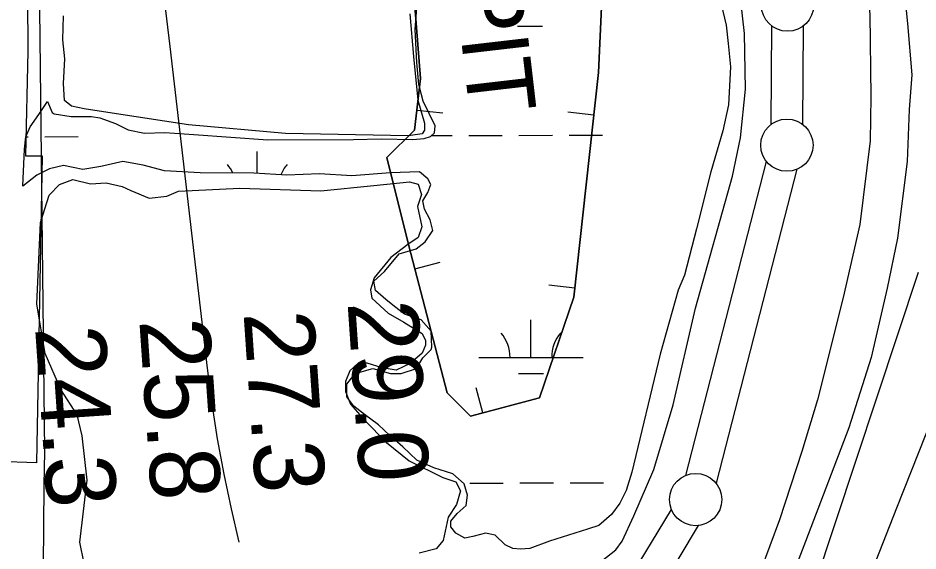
# Model space of a CAD drawing. Extents: x 3355724 to 3393621, y 594744 to 620174.
# Drawn here: x 3387561 to 3388422, y 601973 to 602483 of the extents above; entities that cross this region are included whole.
import ezdxf

# ---------------------------------------------------------------- set-up
doc = ezdxf.new("R2010")
doc.units = 0
for name, color, linetype in [('V-BORW-IDEN', 7, 'Continuous'), ('V-BORW-LINE', 7, 'Continuous'), ('V-LEVE-TOET', 7, 'Continuous'), ('V-RIVR-RANG', 7, 'Continuous'), ('V-ROAD-CNTR', 7, 'Continuous'), ('V-RRAP-RVMT', 7, 'Continuous'), ('V-SITE-VEGE', 7, 'Continuous'), ('V-SURV-LINE', 7, 'Continuous'), ('V-TOPO-MAJR', 7, 'Continuous'), ('V-TOPO-MINR', 7, 'Continuous'), ('V-TOPO-SHOR', 7, 'Continuous'), ('V-WETL-SWMP', 7, 'Continuous')]:
    doc.layers.add(name, color=color, linetype=linetype)

msp = doc.modelspace()

# ---------------------------------------------------------------- linework, layer by layer
at = {"layer": 'V-BORW-LINE'}
for p, q in [((3387942.68, 602395.29), (3387967.53, 602392.52)), ((3388111.98, 602390.46), (3388087.13, 602393.18)), ((3387940.83, 602243.29), (3387965.02, 602249.61)), ((3388093.84, 602224.85), (3388068.99, 602227.57)), ((3388005.89, 602105.32), (3387999.41, 602129.47))]:
    msp.add_line(p, q, dxfattribs=at)
for points in [[(3387947.87, 603316.63), (3388002.91, 603170.46), (3388075.62, 602812.58), (3388123.89, 602591.49), (3388116.43, 602431.11), (3388092.91, 602216.32), (3388060.14, 602119.89), (3387993.92, 602102.11), (3387971.8, 602124.63), (3387935.12, 602265.18), (3387913.95, 602349.92), (3387940.54, 602376.07), (3387946.05, 602425.55), (3387936.81, 602543.89), (3387889.27, 602891.73), (3387859.25, 603019.41), (3387810.27, 603207.54), (3387813.53, 603329.2), (3387887.08, 603328.09), (3387947.87, 603316.63)], [(3387879.82, 602931.95), (3387889.27, 602891.73), (3387936.81, 602543.89), (3387946.05, 602425.55), (3387940.54, 602376.07), (3387913.95, 602349.92), (3387935.12, 602265.18), (3387971.8, 602124.63), (3387993.92, 602102.11), (3388060.14, 602119.89), (3388092.91, 602216.32), (3388116.43, 602431.11), (3388123.89, 602591.49), (3388075.62, 602812.58), (3388002.91, 603170.46), (3387947.87, 603316.63)]]:
    msp.add_lwpolyline(points, dxfattribs=at)
at = {"layer": 'V-LEVE-TOET'}
for points in [[(3388193.51, 603412.27), (3388221.08, 603259.69), (3388257.75, 603077.29), (3388289.46, 602931.67), (3388328.26, 602736.1), (3388357.84, 602605.73), (3388371.25, 602533.6), (3388376.27, 602487.12), (3388377.22, 602408.02), (3388376.66, 602365.68), (3388366.51, 602285.84), (3388350.78, 602215.7), (3388326.12, 602117.77), (3388311.01, 602068.45), (3388289.71, 602003.15), (3388271.14, 601953.12)], [(3388119.82, 601963.73), (3388132.97, 601974.19), (3388139.19, 601982.54), (3388150.21, 602006.86), (3388169.5, 602051.33), (3388188.03, 602113.16), (3388209.25, 602205.52), (3388244.92, 602331.94), (3388252.43, 602368.74), (3388257.14, 602415.26), (3388256.27, 602468.69), (3388248.41, 602539.45), (3388232.85, 602626.83), (3388201.85, 602771.08), (3388182.09, 602871.64), (3388162.39, 602953.46), (3388153.98, 602979.11), (3388143.49, 603004.06), (3388135.79, 603023.46), (3388129.45, 603054.67), (3388110.39, 603153.15), (3388070.83, 603366.76)]]:
    msp.add_lwpolyline(points, dxfattribs=at)
at = {"layer": 'V-ROAD-CNTR'}
msp.add_lwpolyline([(3388422.31, 602239.72), (3388323.16, 601940.46), (3388251.16, 601749.58)], dxfattribs=at)
at = {"layer": 'V-RRAP-RVMT'}
for p, q in [((3387568.81, 602609.22), (3387570.4, 602451.74)), ((3387570.4, 602451.74), (3387568.24, 602351.45)), ((3387568.24, 602351.45), (3387583.88, 602351.47)), ((3387583.88, 602351.47), (3387578.72, 602057.68)), ((3387578.72, 602057.68), (3387313.37, 602065.34))]:
    msp.add_line(p, q, dxfattribs=at)
at = {"layer": 'V-SITE-VEGE'}
for points in [[(3387943.7, 602404.87), (3387949.84, 602382.64), (3387949.86, 602375.9), (3387947.85, 602372.52), (3387934.37, 602370.45), (3387817.06, 602372.77), (3387723.99, 602381.23), (3387651.15, 602392.45), (3387624.17, 602396.41), (3387612.02, 602399.07), (3387605.26, 602404.44), (3387604.54, 602420.61), (3387605.81, 602444.21), (3387603.73, 602462.41), (3387604.33, 602485.33)], [(3387936.02, 602487.5), (3387939.52, 602446.65), (3387943.7, 602404.87)], [(3387624.12, 601961.38), (3387620.01, 601981.59), (3387627.23, 602040.94), (3387622.37, 602083.4), (3387617.59, 602103.61), (3387602, 602127.83), (3387587.06, 602162.17), (3387578.81, 602209.33), (3387582.6, 602287.55), (3387590.61, 602313.87), (3387600.69, 602324.01), (3387613.48, 602328.77), (3387630.35, 602324.78), (3387645.18, 602325.51), (3387660.7, 602322.19), (3387668.8, 602318.17), (3387686.35, 602310.81), (3387703.2, 602312.89), (3387714.65, 602317.64), (3387773.29, 602320.53), (3387850.83, 602318.09), (3387901.38, 602322.97), (3387935.75, 602326.45), (3387943.85, 602324.46), (3387947.25, 602314.36), (3387943.24, 602302.88), (3387947.35, 602283.34), (3387944.01, 602273.22), (3387933.92, 602266.45), (3387917.78, 602254.26), (3387901.66, 602234.66), (3387898.33, 602223.18), (3387899.7, 602215.1), (3387915.26, 602200.99), (3387930.12, 602192.27), (3387947.68, 602181.54), (3387951.07, 602174.81), (3387951.09, 602170.09), (3387947.74, 602162.67), (3387936.31, 602152.52), (3387922.85, 602146.41), (3387909.36, 602148.38), (3387895.19, 602153.06), (3387886.42, 602153.03), (3387878.36, 602145.59), (3387874.35, 602135.46), (3387874.38, 602126.02), (3387879.13, 602113.9), (3387892.67, 602098.44), (3387913.64, 602076.94), (3387935.27, 602059.48), (3387967.68, 602043.4), (3387979.83, 602039.4), (3387984.58, 602030.65), (3387980.58, 602017.83), (3387972.52, 602005.67), (3387969.87, 601992.17), (3387967.88, 601983.4), (3387961.16, 601975.29), (3387945, 601971.19)]]:
    msp.add_lwpolyline(points, dxfattribs=at)
at = {"layer": 'V-SURV-LINE'}
for points in [[(3388281.92, 602381.67), (3388282.39, 602475.83)], [(3388312.39, 602475.68), (3388311.92, 602381.52)], [(3388199.96, 602045.49), (3388277.31, 602346.01)], [(3388306.37, 602338.54), (3388229.01, 602038.01)], [(3388149.08, 601951.38), (3388186.34, 602013.07)], [(3388212.01, 601997.55), (3388174.76, 601935.86)]]:
    msp.add_lwpolyline(points, dxfattribs=at)
for centre in [(3388297.49, 602495.73), (3388296.82, 602361.62), (3388209.5, 602022.41)]:
    msp.add_circle(centre, 25, dxfattribs=at)
at = {"layer": 'V-TOPO-MAJR'}
msp.add_lwpolyline([(3387772.55, 601981.78), (3387765.29, 602013.43), (3387758.2, 602046.87), (3387751.86, 602080.44), (3387746.62, 602114.2), (3387742.13, 602148.1), (3387706.51, 602456.1), (3387695, 602551.84), (3387682.93, 602647.5), (3387670, 602743.04), (3387656.51, 602838.52), (3387633.62, 602995.49), (3387631.13, 603012.42), (3387628.6, 603029.34), (3387626.02, 603046.26), (3387623.41, 603063.16), (3387600.06, 603212.79), (3387585.76, 603304.51), (3387571.47, 603396.24)], dxfattribs=at)
at = {"layer": 'V-TOPO-MINR'}
msp.add_lwpolyline([(3387582.82, 600201.09), (3387598.15, 601075.09), (3387596.87, 601083.33), (3387588.47, 601390.43), (3387585.99, 601503.42), (3387584.33, 601616.42), (3387583.89, 601729.44), (3387584.25, 601842.46), (3387585.93, 602035.9), (3387586.17, 602052.2), (3387586.53, 602068.5), (3387576.65, 602943.68), (3387572.76, 602980.41), (3387568.41, 603017.08), (3387563.34, 603053.67), (3387557.8, 603090.19), (3387557.51, 603091.99), (3387551.3, 603129.33), (3387544.87, 603166.64), (3387538.11, 603203.88), (3387531.12, 603241.09), (3387430.74, 603763.03)], dxfattribs=at)
at = {"layer": 'V-TOPO-SHOR'}
for points in [[(3388218.84, 603473.33), (3388248.96, 603333.88), (3388301.02, 603081.9), (3388327.8, 602930.3), (3388372.33, 602714.03), (3388392.21, 602614.32), (3388406.62, 602534.82), (3388412.2, 602478.2), (3388416.41, 602429), (3388413.82, 602395.96), (3388411.96, 602346.06), (3388402.76, 602272.55), (3388392.81, 602224.65), (3388377.52, 602158.53), (3388356.16, 602091.04), (3388314.72, 601982.36), (3388257.23, 601832.51), (3388198.41, 601674.56), (3388183.71, 601634.06)], [(3388455.05, 602162.52), (3388446.89, 602131.51), (3388436.66, 602101.87), (3388401.83, 602014.31), (3388345.15, 601870.22), (3388332.89, 601830.25), (3388326.08, 601805.44), (3388313.38, 601754.29)]]:
    msp.add_lwpolyline(points, dxfattribs=at)
at = {"layer": 'V-WETL-SWMP'}
for p, q in [((3388038.99, 602475.63), (3388062.99, 602475.69)), ((3387956.56, 602370.77), (3387976.42, 602370.82)), ((3387992.42, 602370.87), (3388024.42, 602370.95)), ((3388040.42, 602370.99), (3388072.42, 602371.08)), ((3388088.42, 602371.12), (3388120.42, 602371.2)), ((3387568.52, 602369.76), (3387570.51, 602369.76)), ((3387586.51, 602369.8), (3387618.51, 602369.89)), ((3387789.92, 602334.63), (3387789.86, 602355.59)), ((3388051.82, 602158.42), (3388051.72, 602194.42)), ((3388001.82, 602158.29), (3388101.82, 602158.55)), ((3388039.86, 602142.95), (3388063.86, 602143.02)), ((3387993.29, 602038.19), (3388025.29, 602038.28)), ((3388041.29, 602038.32), (3388073.29, 602038.4)), ((3388089.29, 602038.44), (3388121.29, 602038.53))]:
    msp.add_line(p, q, dxfattribs=at)
for points in [[(3388230.35, 602511.56), (3388238.56, 602476.53), (3388240.64, 602459.01), (3388242.73, 602436.77)], [(3387565.69, 602322.5), (3387567.08, 602357.77), (3387568.43, 602369.54), (3387572.55, 602379.23), (3387580.81, 602391.02), (3387589.07, 602403.49), (3387593.53, 602393.09), (3387595.56, 602391.75), (3387611.75, 602389.11), (3387631.3, 602389.17), (3387639.39, 602387.85), (3387654.24, 602382.51), (3387666.4, 602376.48), (3387681.92, 602373.16), (3387701.46, 602373.9), (3387729.11, 602371.96), (3387799.92, 602366.8), (3387882.17, 602367.07), (3387908.46, 602367.83), (3387938.8, 602367.25), (3387949.58, 602367.96), (3387955.64, 602370.01), (3387959.68, 602373.39), (3387960.33, 602380.13), (3387948.79, 602403.69), (3387944.69, 602419.86), (3387942.6, 602440.75), (3387941.15, 602472.43), (3387943.09, 602497.38)], [(3388242.73, 602436.77), (3388240.83, 602400.35), (3388235.52, 602375.39), (3388224.18, 602336.25), (3388210.2, 602281.6), (3388198.89, 602237.07), (3388192.87, 602222.89), (3388175.54, 602161.48), (3388148.26, 602048.81), (3388142.93, 602031.26), (3388136.9, 602019.1), (3388128.84, 602008.29), (3388116.74, 601997.46), (3388105.97, 601994.06), (3388069.6, 601982.48), (3388050.75, 601975.68), (3388041.98, 601974.97), (3388034.56, 601975.62), (3388027.14, 601978.97), (3388017.67, 601988.38), (3388008.22, 601990.37), (3388003.51, 601989.01), (3387996.1, 601986.96), (3387988.69, 601985.59), (3387979.91, 601990.28), (3387975.17, 601996.33), (3387975.15, 602001.72), (3387981.2, 602009.16), (3387989.94, 602016.6), (3387991.25, 602026.72), (3387987.84, 602037.49), (3387977.03, 602046.9), (3387958.8, 602052.91), (3387942.6, 602060.27), (3387929.08, 602073.04), (3387916.9, 602083.78), (3387906.08, 602093.86), (3387892.57, 602103.93), (3387882.43, 602111.98), (3387875.66, 602120.73), (3387875.62, 602132.86), (3387883.68, 602143), (3387900.52, 602147.78), (3387917.39, 602143.11), (3387927.5, 602143.15), (3387942.31, 602147.91), (3387948.35, 602158.05), (3387956.41, 602166.16), (3387957.08, 602168.19), (3387956.35, 602183.69), (3387946.88, 602194.45), (3387930.68, 602199.79), (3387921.22, 602207.17), (3387913.11, 602213.89), (3387902.97, 602222.62), (3387901.59, 602231.38), (3387911.67, 602240.85), (3387925.77, 602257.75), (3387941.94, 602262.52), (3387950.68, 602269.29), (3387958.06, 602280.1), (3387955.33, 602290.21), (3387949.91, 602300.3), (3387948.53, 602308.39), (3387953.23, 602316.49), (3387955.9, 602323.92), (3387953.18, 602329.3), (3387945.07, 602336.02), (3387917.43, 602335.25), (3387880.36, 602332.44), (3387849.34, 602334.36), (3387818.33, 602332.91), (3387786.64, 602334.83), (3387735.4, 602335.33), (3387701.01, 602337.24), (3387680.77, 602342.57), (3387661.21, 602345.88), (3387640.33, 602341.09), (3387622.81, 602338.34), (3387604.59, 602342.32), (3387591.12, 602338.91), (3387579, 602332.8), (3387565.69, 602322.5)]]:
    msp.add_lwpolyline(points, dxfattribs=at)
for centre, start, end in [((3387734.71, 602319.92), 25.37072, 40.92184), ((3387845.2, 602320.21), 139.37818, 158.26721), ((3387996.57, 602158.75), 359.37818, 40.92184), ((3388107.06, 602159.04), 139.37818, 180.92184)]:
    msp.add_arc(centre, 35.25, start, end, dxfattribs=at)

# ---------------------------------------------------------------- texts
at = {"layer": 'V-BORW-IDEN'}
msp.add_text('BORROW PIT', height=64, rotation=276.61248, dxfattribs=at).set_placement((3387930.05, 602937.04))
at = {"layer": 'V-RIVR-RANG'}
for s, p in [('29.0', (3387876.29, 602211.07)), ('27.3', (3387776.74, 602201.1)), ('25.8', (3387676.99, 602194.03)), ('24.3', (3387577.24, 602186.96))]:
    msp.add_text(s, height=67, rotation=273.90833, dxfattribs=at).set_placement(p)

doc.saveas('drawing.dxf')
